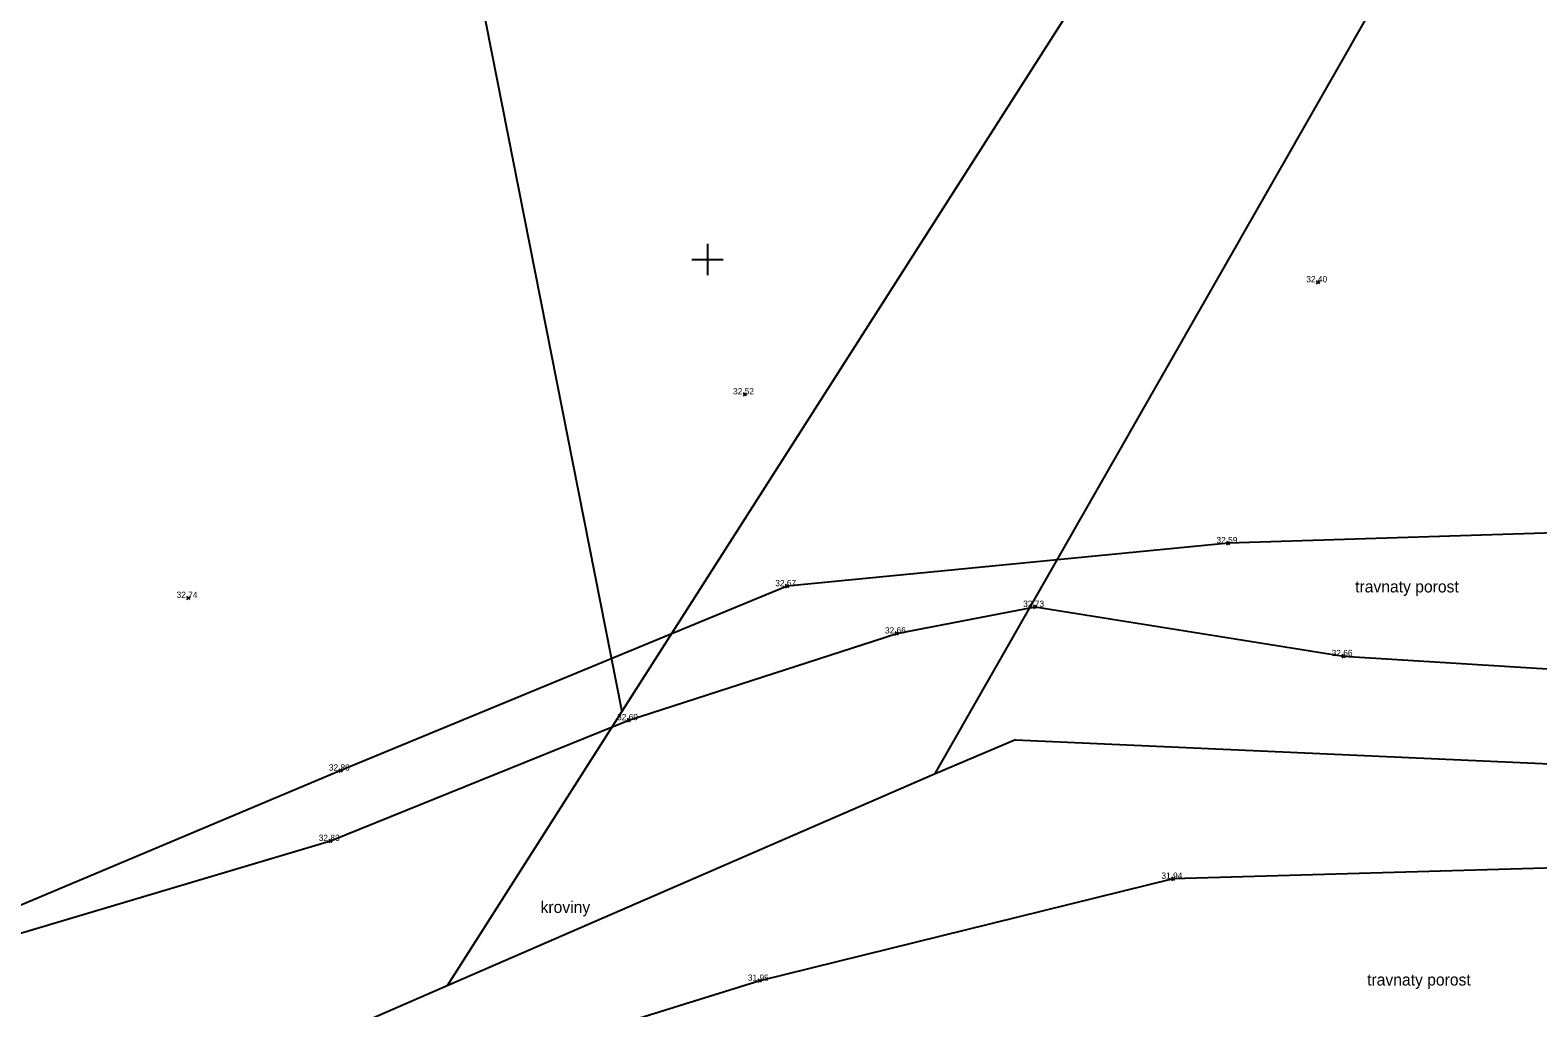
# Model space of a CAD drawing. Extents: x -772865 to -772533, y -1034366 to -1034132.
# Drawn here: x -772667.35 to -772628.73, y -1034219.15 to -1034194.13 of the extents above; entities that cross this region are included whole.
import ezdxf

# ---------------------------------------------------------------- set-up
doc = ezdxf.new("R2010")
doc.units = 0
for name, color, linetype in [('body', 7, 'Continuous'), ('KM_hranice', 7, 'Continuous'), ('mistni_popis', 7, 'Continuous'), ('oddeleni_ploch', 7, 'Continuous'), ('souradnicova_sit', 7, 'Continuous'), ('stromy_kere', 7, 'Continuous'), ('vyskove_koty', 7, 'Continuous')]:
    doc.layers.add(name, color=color, linetype=linetype)

msp = doc.modelspace()

# ---------------------------------------------------------------- linework, layer by layer
at = {"layer": 'body'}
for p, q in [((-772634.32, -1034200.62), (-772634.4, -1034200.54)), ((-772634.4, -1034200.62), (-772634.32, -1034200.54)), ((-772649, -1034203.49), (-772649.08, -1034203.41)), ((-772649.08, -1034203.49), (-772649, -1034203.41)), ((-772636.62, -1034207.3), (-772636.7, -1034207.22)), ((-772636.7, -1034207.3), (-772636.62, -1034207.22)), ((-772647.92, -1034208.4), (-772648, -1034208.32)), ((-772648, -1034208.4), (-772647.92, -1034208.32)), ((-772663.25, -1034208.7), (-772663.33, -1034208.62)), ((-772663.33, -1034208.7), (-772663.25, -1034208.62)), ((-772641.57, -1034208.93), (-772641.65, -1034208.85)), ((-772641.65, -1034208.93), (-772641.57, -1034208.85)), ((-772645.11, -1034209.61), (-772645.19, -1034209.53)), ((-772645.19, -1034209.61), (-772645.11, -1034209.53)), ((-772633.67, -1034210.19), (-772633.75, -1034210.11)), ((-772633.75, -1034210.19), (-772633.67, -1034210.11)), ((-772651.97, -1034211.83), (-772652.05, -1034211.75)), ((-772652.05, -1034211.83), (-772651.97, -1034211.75)), ((-772659.35, -1034213.12), (-772659.43, -1034213.04)), ((-772659.43, -1034213.12), (-772659.35, -1034213.04)), ((-772659.61, -1034214.92), (-772659.69, -1034214.84)), ((-772659.69, -1034214.92), (-772659.61, -1034214.84)), ((-772638.03, -1034215.89), (-772638.11, -1034215.81)), ((-772638.11, -1034215.89), (-772638.03, -1034215.81)), ((-772648.62, -1034218.5), (-772648.7, -1034218.42)), ((-772648.7, -1034218.5), (-772648.62, -1034218.42))]:
    msp.add_line(p, q, dxfattribs=at)
at = {"layer": 'KM_hranice'}
for p, q in [((-772667.23, -1034135.57), (-772652.19, -1034211.57)), ((-772632.9, -1034181.34), (-772652.19, -1034211.57)), ((-772628.96, -1034186.51), (-772644.19, -1034213.17)), ((-772652.19, -1034211.57), (-772656.67, -1034218.59)), ((-772642.11, -1034212.29), (-772644.19, -1034213.17)), ((-772642.11, -1034212.29), (-772625.89, -1034213.02)), ((-772644.19, -1034213.17), (-772656.67, -1034218.59)), ((-772656.67, -1034218.59), (-772680.54, -1034228.95))]:
    msp.add_line(p, q, dxfattribs=at)
at = {"layer": 'oddeleni_ploch'}
msp.add_lwpolyline([(-772574.1, -1034196.14), (-772586.87, -1034201.34), (-772598.23, -1034205.06), (-772614.53, -1034207.42), (-772626.93, -1034206.95), (-772636.66, -1034207.26), (-772647.96, -1034208.36), (-772659.39, -1034213.08), (-772672.58, -1034218.62), (-772687.49, -1034225.14), (-772703.01, -1034232.02), (-772714.35, -1034236.9), (-772728.88, -1034243.07), (-772737.97, -1034245.74), (-772746.8, -1034246.99), (-772753.85, -1034250.11), (-772762.71, -1034257.3), (-772782.05, -1034269.18), (-772797.09, -1034276.39), (-772810.61, -1034282.39), (-772816.13, -1034284.08), (-772822.76, -1034283.4), (-772826.73, -1034280.27)], dxfattribs=at)
at = {"layer": 'souradnicova_sit'}
for p, q in [((-772650, -1034199.6), (-772650, -1034200.4)), ((-772650.4, -1034200), (-772649.6, -1034200))]:
    msp.add_line(p, q, dxfattribs=at)
at = {"layer": 'stromy_kere'}
for points in [[(-772703.51, -1034234.42), (-772694.98, -1034230.19), (-772692.57, -1034230.49), (-772690.11, -1034226.84), (-772682.67, -1034224.98), (-772675.51, -1034221.67), (-772672.25, -1034219.76), (-772669.56, -1034219.99), (-772667.68, -1034217.27), (-772659.65, -1034214.88), (-772652.01, -1034211.79), (-772645.15, -1034209.57), (-772641.61, -1034208.89), (-772633.71, -1034210.15), (-772627.94, -1034210.51), (-772625.02, -1034208.48), (-772619.49, -1034209.69), (-772612.97, -1034209.94), (-772600.85, -1034207.82), (-772593.5, -1034206.2), (-772588.67, -1034204.86)], [(-772583.42, -1034211.72), (-772590.3, -1034214.78), (-772599.43, -1034217.31), (-772610.6, -1034216.68), (-772621.69, -1034215.38), (-772638.07, -1034215.85), (-772648.66, -1034218.46), (-772661.39, -1034222.42), (-772671.31, -1034228.13), (-772675.64, -1034228.98), (-772682.86, -1034232.81), (-772685.07, -1034236.11), (-772686.87, -1034236.8), (-772697.8, -1034241.28), (-772703.73, -1034242.07)]]:
    msp.add_lwpolyline(points, dxfattribs=at)

# ---------------------------------------------------------------- texts
at = {"layer": 'mistni_popis'}
for s, p in [('travnaty porost', (-772633.413, -1034208.52)), ('kroviny', (-772654.274, -1034216.724)), ('travnaty porost', (-772633.107, -1034218.582))]:
    msp.add_text(s, height=0.3, dxfattribs=at).set_placement(p)
at = {"layer": 'vyskove_koty'}
for s, p in [('32.40', (-772634.665, -1034200.58)), ('32.52', (-772649.345, -1034203.45)), ('32.59', (-772636.965, -1034207.26)), ('32.74', (-772663.595, -1034208.66)), ('32.67', (-772648.265, -1034208.36)), ('32.73', (-772641.915, -1034208.89)), ('32.66', (-772645.455, -1034209.57)), ('32.66', (-772634.015, -1034210.15)), ('32.69', (-772652.315, -1034211.79)), ('32.80', (-772659.695, -1034213.08)), ('32.83', (-772659.955, -1034214.88)), ('31.94', (-772638.375, -1034215.85)), ('31.95', (-772648.965, -1034218.46))]:
    msp.add_text(s, height=0.16, dxfattribs=at).set_placement(p)

doc.saveas('drawing.dxf')
